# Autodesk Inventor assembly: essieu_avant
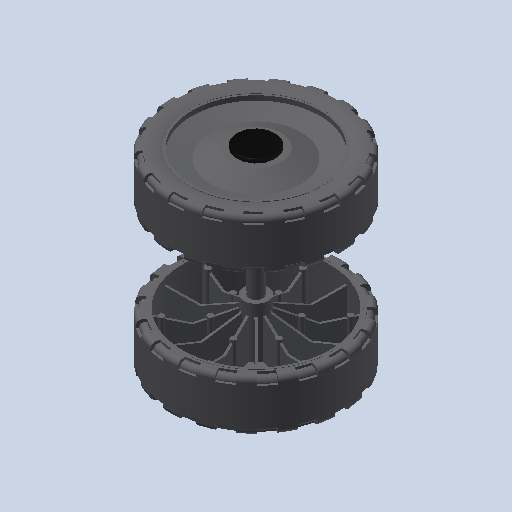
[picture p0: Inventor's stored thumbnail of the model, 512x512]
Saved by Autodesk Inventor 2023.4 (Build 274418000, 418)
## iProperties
Created: 2011-01
Part Number: essieu_avant
Document SubType Name: Assembly
Designer: eric
Mass: 610.809 g
Surface Area: 3296.9 cm^2
Volume: 610.809 cm^3
Density: 1 g/cm^3
Author: eric
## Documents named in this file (2)
- C:\Users\bruno\Documents\1-Cours-2024-25\TSsI\7-Dynamique\chariot de golf\chariot_de_golf\chariot_de_golf_trolem\essieu_avant.iam
- C:\Users\bruno\Documents\1-Cours-2024-25\TSsI\7-Dynamique\chariot de golf\chariot_de_golf\chariot_de_golf_trolem\5.1roues_montees_axe_Defaut.iam
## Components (1 placed, 1 different names)
1. essieu:1 [sub-assembly]
